// Mitsubishi GX Works2 project: 变址使用案例   PLC: FX3U/FX3UC

PROGRAM MAIN
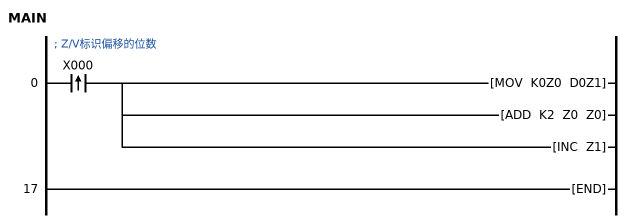
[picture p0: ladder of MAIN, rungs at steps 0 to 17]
; Z/V标识偏移的位数
0     LDP     X000
      MOV     K0Z0 D0Z1
        [note] K0Z0：K(0+Z0值)
      ADD     K2 Z0 Z0
        [note] Z0自+2
      INC     Z1
        [note] Z1自+1
17    END
END_PROGRAM

// device comments not shown above
D0  ; D(0+Z1):D0开始偏移Z1值个位
